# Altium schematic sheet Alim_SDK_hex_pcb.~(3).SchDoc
size 297 x 209 mm
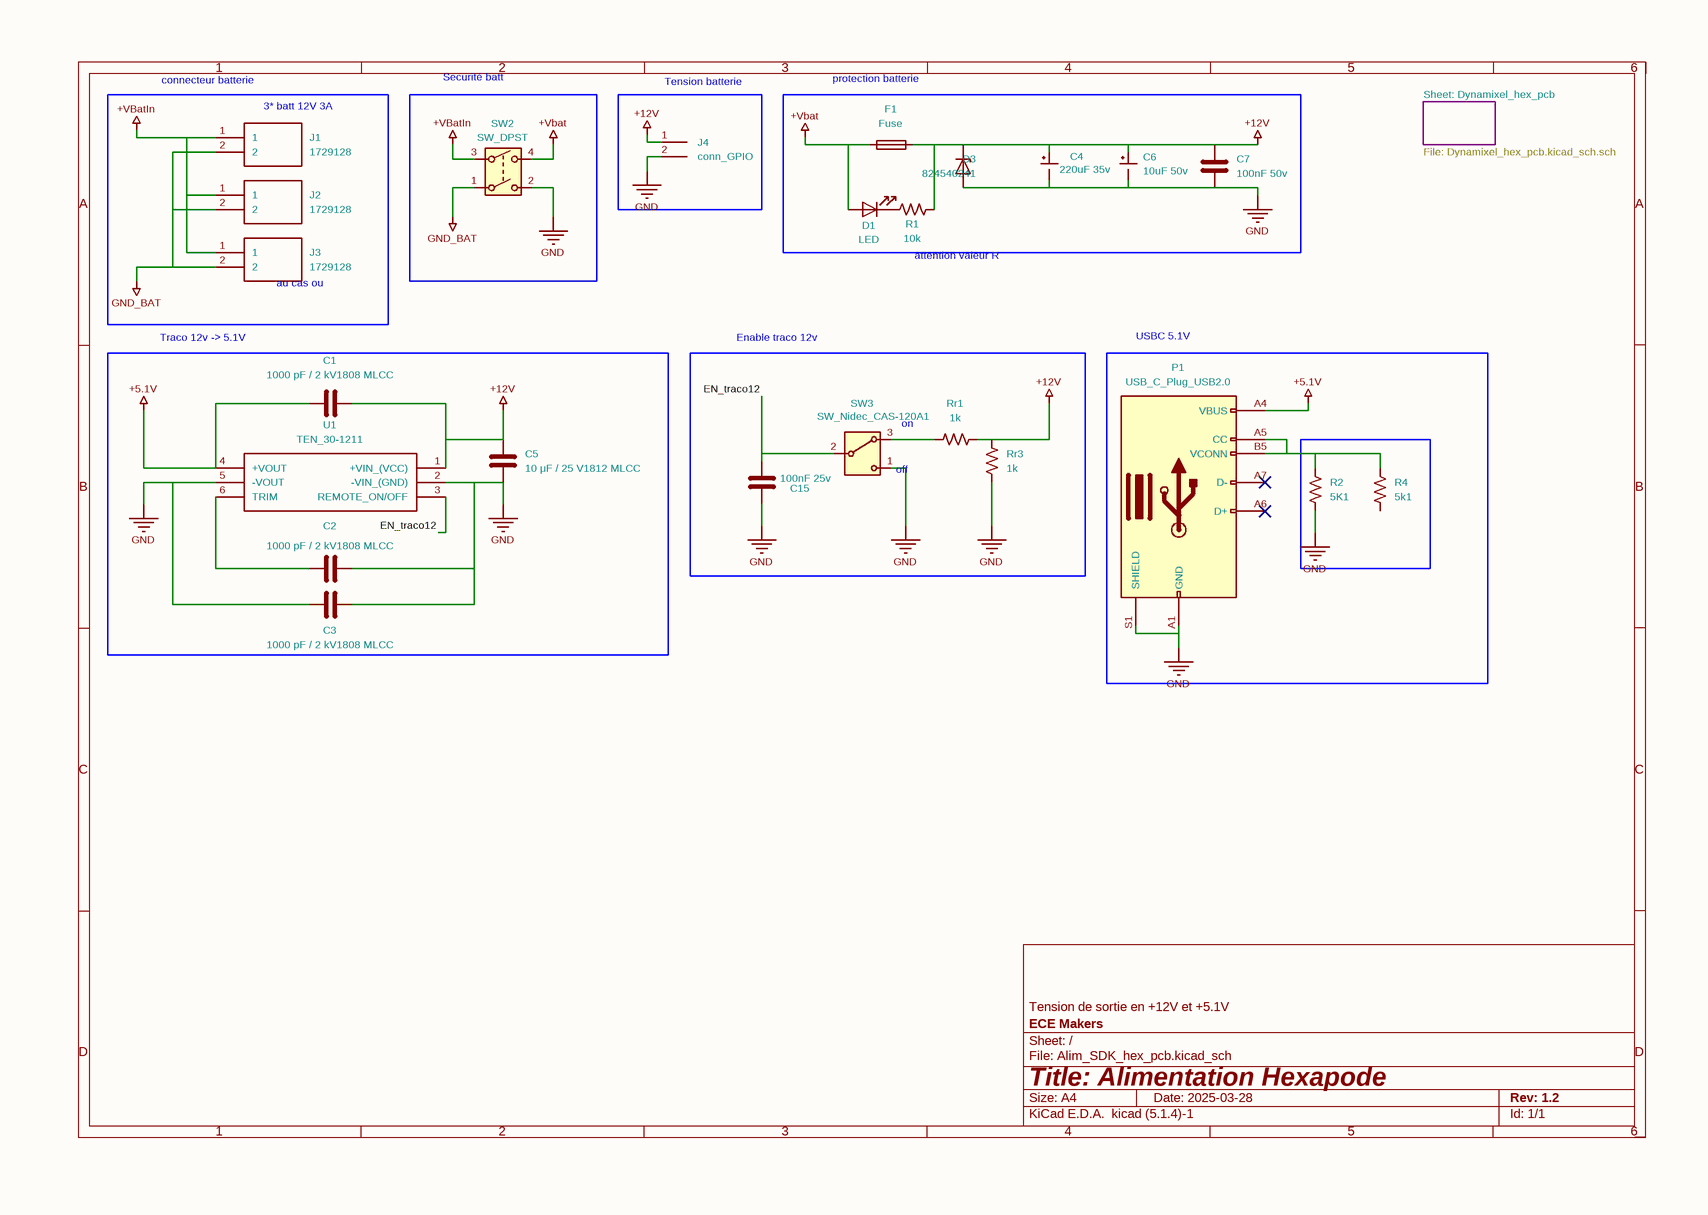
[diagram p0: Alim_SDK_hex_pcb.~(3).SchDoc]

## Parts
C1  1000 pF / 2 kV1808 MLCC  [C_0603_1608Metric]
C2  1000 pF / 2 kV1808 MLCC  [C_0603_1608Metric]
C3  1000 pF / 2 kV1808 MLCC  [C_0603_1608Metric]
C4  220uF 35v  [CP_Wurth_WCAP-HSG5-D8L10.5]
C5  10 μF / 25 V1812 MLCC  [C_0603_1608Metric]
C6  10uF 50v  [CP_Wurth_WCAP-HSG5-D5L5.8]
C7  100nF 50v  [C_0603_1608Metric]
C15  100nF 25v  [C_0603_1608Metric]
D1  LED  [LED_0603_1608Metric_Pad1.05x0.95mm_HandSolder]
D3  824540241  [D_0603_1608Metric]
F1  Fuse
J1  1729128  [691250610002]
J2  1729128  [691250610002]
J3  1729128  [691250610002]
J4  conn_GPIO  [PinHeader_1x02_P2.54mm_Vertical]
P1  USB_C_Plug_USB2.0
R1  10k  [R_0603_1608Metric_Pad0.98x0.95mm_HandSolder]
R2  5K1  [R_0201_0603Metric]
R4  5k1  [R_0201_0603Metric]
Rr1  1k  [R_0201_0603Metric]
Rr3  1k  [R_0201_0603Metric]
SW2  SW_DPST
SW3  SW_Nidec_CAS-120A1  [SW_Slide_SPDT_Straight_CK_OS102011MS2Q]
U1  TEN_30-1211  [Converter_DCDC_TRACO_THN30-xxxx_THT]

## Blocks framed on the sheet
Securité batt: SW2
Tension batterie: J4
protection batterie: C4 C6 C7 D1 D3 F1 R1
Traco 12v -> 5.1V: C1-C3 C5 U1
USBC 5.1V /: P1 R2 R4

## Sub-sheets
Dynamixel_hex_pcb = Dynamixel_hex_pcb.SchDoc: no entries

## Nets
+5.1V: C1.1 P1.A4(VBUS) U1.4(+VOUT)
+12V: C1.2 C4.1 C5.1 C6.1 C7.1 D3.1(K) F1.2 J4.1(Pin_1) R1.2 Rr1.2 Rr3.2 U1.1(+VIN_(VCC))
+Vbat: D1.2(A) F1.1 SW2.4
+VBatIn: J1.1 J2.1 J3.1 SW2.3
GND: C2.2 C3.1 C3.2 C4.2 C5.2 C6.2 C7.2 C15.2 D3.2(A) J4.2(Pin_2) P1.A1(GND) P1.S1(SHIELD) R2.2 Rr3.1 SW2.2 SW3.1(C) U1.2(-VIN_(GND)) U1.5(-VOUT)
GND_BAT: J1.2 J2.2 J3.2 SW2.1
EN_traco12: C15.1 SW3.2(B) U1.3(REMOTE_ON/OFF)
NetC2_1: C2.1 U1.6(TRIM)
NetD1_1: D1.1(K) R1.1
NetP1_A5: P1.A5(CC) P1.B5(VCONN) R2.1 R4.1
NetRr1_1: Rr1.1 SW3.3(A)

Not connected (* = marked no-connect by the designer): P1 A6(D+)* A7(D-)* A9(VBUS) A12(GND) B1(GND) B4(VBUS) B9(VBUS) B12(GND); R4 2

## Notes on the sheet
- (near J1) connecteur batterie
- (near J1) 3* batt 12V 3A
- File: Dynamixel_hex_pcb.kicad_sch.sch
- Sheet: Dynamixel_hex_pcb
- (near J3) au cas ou
- attention valeur R
- Enable traco 12v
- on
- (near SW3) off

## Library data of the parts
C1-C3 C5 C7 C15 = C: Description: Unpolarized capacitor
C4 C6 = C_Polarized_Small_US: Description: Polarized capacitor, small US symbol
D1 = LED: Description: Light emitting diode
D3 = D_Zener: Description: Zener diode
J1-J3 = 1729128: Manufacturer_Name: Phoenix Contact; Description: PCB terminal block, nominal current: 13.5 A, rated voltage (III/2): 400 V, nominal cross section: 1.5 mm?, Number of potentials: 2, Number of rows: 1, Number of positions per row: 2, product range: MKDSN 1,5, pitch: 5.08 mm, connection method: Screw connection with tension sleeve, mounting: Wave soldering, conductor/PCB connection direction: 0 ?, color: green, Pin layout: Linear pinning, Solder pin [P]: 3.5 mm, type of packaging: packed in cardboard
J4 = Conn_01x02_Socket: Description: Generic connector, single row, 01x02, script generated
P1 = USB_C_Plug_USB2.0: Description: USB 2.0-only Type-C Plug connector
R1 R2 R4 Rr1 Rr3 = R_US: Description: Resistor, US symbol
SW2 = SW_DPST: Description: Double Pole Single Throw (DPST) Switch
SW3 = SW_Nidec_CAS-120A1: Description: Switch, single pole double throw
U1 = TEN_30-1211: Manufacturer_Name: Traco Power; Manufacturer_Part_Number: TEN 30-1211; Description: 30 Watt DC/DC converter, industrial, 2:1 input, encapsulated, 2" x 1" metal package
